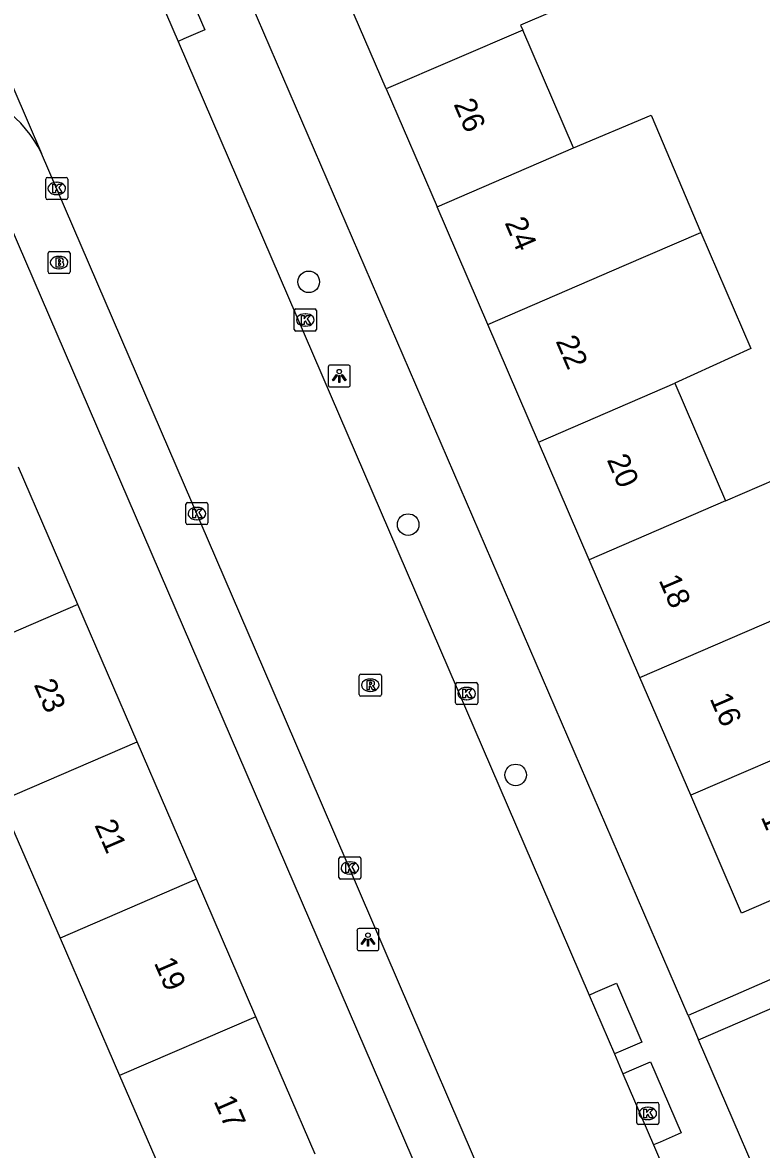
# Model space of a CAD drawing. Extents: x 159353 to 160616, y 385893 to 387321.
# Drawn here: x 159544.3 to 159577.9, y 386254.5 to 386305.6 of the extents above; entities that cross this region are included whole.
import ezdxf

# ---------------------------------------------------------------- set-up
doc = ezdxf.new("R2010")
doc.units = 0
for name, color, linetype in [('IMGEO_Boom', 7, 'Continuous'), ('IMGEO_Brandkraan', 7, 'Continuous'), ('IMGEO_Kolk', 7, 'Continuous'), ('IMGEO_Lichtpunt', 7, 'Continuous'), ('IMGEO_Pand', 7, 'Continuous'), ('IMGEO_Pand_nummerreeks', 7, 'Continuous'), ('IMGEO_Rijbaan_lokaal_gesloten', 7, 'Continuous'), ('IMGEO_Rijbaan_lokaal_open', 7, 'Continuous'), ('IMGEO_Rioolput', 7, 'Continuous'), ('IMGEO_Voetpad_open', 7, 'Continuous')]:
    doc.layers.add(name, color=color, linetype=linetype)

msp = doc.modelspace()

# ---------------------------------------------------------------- linework, layer by layer
at = {"layer": 'IMGEO_Boom'}
for centre in [(159557.321, 386293.872), (159561.831, 386282.862), (159566.708, 386271.508)]:
    msp.add_circle(centre, 0.489, dxfattribs=at)
at = {"layer": 'IMGEO_Brandkraan'}
for p, q in [((159545.496, 386294.321), (159545.496, 386295.173)), ((159545.571, 386295.247), (159546.423, 386295.247)), ((159545.984, 386295.027), (159546.009, 386295.027)), ((159546.497, 386295.173), (159546.497, 386294.321)), ((159546.007, 386294.467), (159545.982, 386294.467)), ((159546.423, 386294.247), (159545.571, 386294.247))]:
    msp.add_line(p, q, dxfattribs=at)
for points in [[(159545.496, 386294.321), (159545.496, 386295.173)], [(159545.571, 386295.247), (159546.423, 386295.247)], [(159545.844, 386294.947), (159545.844, 386294.547), (159546.057, 386294.547)], [(159546.075, 386294.947), (159545.844, 386294.947)], [(159546.497, 386295.173), (159546.497, 386294.321)], [(159546.023, 386294.866), (159545.969, 386294.866), (159545.969, 386294.79)], [(159545.969, 386294.79), (159546.022, 386294.79)], [(159546.031, 386294.714), (159545.969, 386294.714), (159545.969, 386294.633)], [(159545.969, 386294.633), (159546.031, 386294.633)], [(159546.423, 386294.247), (159545.571, 386294.247)]]:
    msp.add_lwpolyline(points, dxfattribs=at)
for centre, radius, start, end in [((159545.573, 386295.171), 0.0765, 91.552, 178.448), ((159545.573, 386295.171), 0.0765, 91.552, 178.448), ((159546.079, 386294.802), 0.145, 59.4692, 91.5367), ((159546.104, 386294.849), 0.0922, 285.5137, 58.1501), ((159546.421, 386295.171), 0.0765, 1.552, 88.448), ((159546.421, 386295.171), 0.0765, 1.552, 88.448), ((159546.024, 386294.828), 0.0379, 267.8285, 90.9355), ((159546.032, 386294.673), 0.0404, 269.8759, 90.5077), ((159546.063, 386294.798), 0.251, 268.6676, 293.5347), ((159546.109, 386294.657), 0.105, 301.3115, 78.989), ((159545.573, 386294.323), 0.0765, 181.552, 268.448), ((159545.573, 386294.323), 0.0765, 181.552, 268.448), ((159546.421, 386294.323), 0.0765, 271.552, 358.448), ((159546.421, 386294.323), 0.0765, 271.552, 358.448)]:
    msp.add_arc(centre, radius, start, end, dxfattribs=at)
for centre, major_axis, ratio, start_param, end_param in [((159545.983, 386294.747), (-0.387, 0.002), 0.722429, 4.712389, 7.853982), ((159546.008, 386294.747), (-0.39, 0.002), 0.717154, 1.570796, 4.712389)]:
    msp.add_ellipse(centre, major_axis=major_axis, ratio=ratio, start_param=start_param, end_param=end_param, dxfattribs=at)
at = {"layer": 'IMGEO_Kolk'}
for p, q in [((159545.39, 386297.68), (159545.39, 386298.532)), ((159545.465, 386298.606), (159546.317, 386298.606)), ((159546.391, 386298.532), (159546.391, 386297.68)), ((159545.878, 386298.386), (159545.903, 386298.386)), ((159546.317, 386297.606), (159545.465, 386297.606)), ((159545.901, 386297.826), (159545.876, 386297.826)), ((159556.665, 386291.716), (159556.665, 386292.568)), ((159556.74, 386292.642), (159557.592, 386292.642)), ((159557.153, 386292.422), (159557.178, 386292.422)), ((159557.666, 386292.568), (159557.666, 386291.716)), ((159557.176, 386291.862), (159557.151, 386291.862)), ((159557.592, 386291.642), (159556.74, 386291.642)), ((159551.746, 386282.935), (159551.746, 386283.787)), ((159551.821, 386283.861), (159552.673, 386283.861)), ((159552.234, 386283.641), (159552.259, 386283.641)), ((159552.747, 386283.787), (159552.747, 386282.935)), ((159552.673, 386282.861), (159551.821, 386282.861)), ((159552.257, 386283.081), (159552.232, 386283.081)), ((159563.985, 386274.771), (159563.985, 386275.623)), ((159564.06, 386275.697), (159564.912, 386275.697)), ((159564.473, 386275.477), (159564.498, 386275.477)), ((159564.986, 386275.623), (159564.986, 386274.771)), ((159564.912, 386274.697), (159564.06, 386274.697)), ((159564.496, 386274.917), (159564.471, 386274.917)), ((159558.762, 386267.787), (159559.614, 386267.787)), ((159558.687, 386266.861), (159558.687, 386267.713)), ((159559.175, 386267.567), (159559.2, 386267.567)), ((159559.688, 386267.713), (159559.688, 386266.861)), ((159559.614, 386266.787), (159558.762, 386266.787)), ((159559.198, 386267.007), (159559.173, 386267.007)), ((159572.203, 386255.727), (159572.203, 386256.579)), ((159572.278, 386256.653), (159573.13, 386256.653)), ((159573.204, 386256.579), (159573.204, 386255.727)), ((159572.691, 386256.433), (159572.716, 386256.433)), ((159573.13, 386255.653), (159572.278, 386255.653)), ((159572.714, 386255.873), (159572.689, 386255.873))]:
    msp.add_line(p, q, dxfattribs=at)
for points in [[(159545.39, 386297.68), (159545.39, 386298.532)], [(159545.465, 386298.606), (159546.317, 386298.606)], [(159546.391, 386298.532), (159546.391, 386297.68)], [(159545.711, 386298.306), (159545.834, 386298.306), (159545.834, 386298.155), (159545.964, 386298.306), (159546.128, 386298.306), (159545.982, 386298.155), (159546.135, 386297.906), (159545.983, 386297.906), (159545.898, 386298.07), (159545.834, 386298.003), (159545.834, 386297.906), (159545.711, 386297.906), (159545.711, 386298.306)], [(159546.317, 386297.606), (159545.465, 386297.606)], [(159556.665, 386291.716), (159556.665, 386292.568)], [(159556.74, 386292.642), (159557.592, 386292.642)], [(159556.986, 386292.342), (159557.109, 386292.342), (159557.109, 386292.191), (159557.239, 386292.342), (159557.403, 386292.342), (159557.257, 386292.191), (159557.41, 386291.942), (159557.258, 386291.942), (159557.173, 386292.106), (159557.109, 386292.039), (159557.109, 386291.942), (159556.986, 386291.942), (159556.986, 386292.342)], [(159557.666, 386292.568), (159557.666, 386291.716)], [(159557.592, 386291.642), (159556.74, 386291.642)], [(159551.746, 386282.935), (159551.746, 386283.787)], [(159551.821, 386283.861), (159552.673, 386283.861)], [(159552.747, 386283.787), (159552.747, 386282.935)], [(159552.067, 386283.561), (159552.19, 386283.561), (159552.19, 386283.41), (159552.32, 386283.561), (159552.484, 386283.561), (159552.338, 386283.41), (159552.491, 386283.161), (159552.339, 386283.161), (159552.254, 386283.325), (159552.19, 386283.258), (159552.19, 386283.161), (159552.067, 386283.161), (159552.067, 386283.561)], [(159552.673, 386282.861), (159551.821, 386282.861)], [(159563.985, 386274.771), (159563.985, 386275.623)], [(159564.06, 386275.697), (159564.912, 386275.697)], [(159564.986, 386275.623), (159564.986, 386274.771)], [(159564.306, 386275.397), (159564.429, 386275.397), (159564.429, 386275.246), (159564.559, 386275.397), (159564.723, 386275.397), (159564.577, 386275.246), (159564.73, 386274.997), (159564.578, 386274.997), (159564.493, 386275.161), (159564.429, 386275.094), (159564.429, 386274.997), (159564.306, 386274.997), (159564.306, 386275.397)], [(159564.912, 386274.697), (159564.06, 386274.697)], [(159558.762, 386267.787), (159559.614, 386267.787)], [(159558.687, 386266.861), (159558.687, 386267.713)], [(159559.008, 386267.487), (159559.131, 386267.487), (159559.131, 386267.336), (159559.261, 386267.487), (159559.425, 386267.487), (159559.279, 386267.336), (159559.432, 386267.087), (159559.28, 386267.087), (159559.195, 386267.251), (159559.131, 386267.184), (159559.131, 386267.087), (159559.008, 386267.087), (159559.008, 386267.487)], [(159559.688, 386267.713), (159559.688, 386266.861)], [(159559.614, 386266.787), (159558.762, 386266.787)], [(159572.203, 386255.727), (159572.203, 386256.579)], [(159572.278, 386256.653), (159573.13, 386256.653)], [(159573.204, 386256.579), (159573.204, 386255.727)], [(159572.524, 386256.353), (159572.647, 386256.353), (159572.647, 386256.202), (159572.777, 386256.353), (159572.941, 386256.353), (159572.795, 386256.202), (159572.948, 386255.953), (159572.796, 386255.953), (159572.711, 386256.117), (159572.647, 386256.05), (159572.647, 386255.953), (159572.524, 386255.953), (159572.524, 386256.353)], [(159573.13, 386255.653), (159572.278, 386255.653)]]:
    msp.add_lwpolyline(points, dxfattribs=at)
for centre, start, end in [((159545.467, 386298.53), 91.552, 178.448), ((159545.467, 386298.53), 91.552, 178.448), ((159546.315, 386298.53), 1.552, 88.448), ((159546.315, 386298.53), 1.552, 88.448), ((159545.467, 386297.682), 181.552, 268.448), ((159545.467, 386297.682), 181.552, 268.448), ((159546.315, 386297.682), 271.552, 358.448), ((159546.315, 386297.682), 271.552, 358.448), ((159556.742, 386292.566), 91.552, 178.448), ((159556.742, 386292.566), 91.552, 178.448), ((159557.59, 386292.566), 1.552, 88.448), ((159557.59, 386292.566), 1.552, 88.448), ((159556.742, 386291.718), 181.552, 268.448), ((159556.742, 386291.718), 181.552, 268.448), ((159557.59, 386291.718), 271.552, 358.448), ((159557.59, 386291.718), 271.552, 358.448), ((159551.823, 386283.785), 91.552, 178.448), ((159551.823, 386283.785), 91.552, 178.448), ((159552.671, 386283.785), 1.552, 88.448), ((159552.671, 386283.785), 1.552, 88.448), ((159551.823, 386282.937), 181.552, 268.448), ((159551.823, 386282.937), 181.552, 268.448), ((159552.671, 386282.937), 271.552, 358.448), ((159552.671, 386282.937), 271.552, 358.448), ((159564.062, 386275.621), 91.552, 178.448), ((159564.062, 386275.621), 91.552, 178.448), ((159564.91, 386275.621), 1.552, 88.448), ((159564.91, 386275.621), 1.552, 88.448), ((159564.062, 386274.773), 181.552, 268.448), ((159564.062, 386274.773), 181.552, 268.448), ((159564.91, 386274.773), 271.552, 358.448), ((159564.91, 386274.773), 271.552, 358.448), ((159558.764, 386267.711), 91.552, 178.448), ((159558.764, 386267.711), 91.552, 178.448), ((159559.612, 386267.711), 1.552, 88.448), ((159559.612, 386267.711), 1.552, 88.448), ((159558.764, 386266.863), 181.552, 268.448), ((159558.764, 386266.863), 181.552, 268.448), ((159559.612, 386266.863), 271.552, 358.448), ((159559.612, 386266.863), 271.552, 358.448), ((159572.28, 386256.577), 91.552, 178.448), ((159572.28, 386256.577), 91.552, 178.448), ((159573.128, 386256.577), 1.552, 88.448), ((159573.128, 386256.577), 1.552, 88.448), ((159572.28, 386255.729), 181.552, 268.448), ((159572.28, 386255.729), 181.552, 268.448), ((159573.128, 386255.729), 271.552, 358.448), ((159573.128, 386255.729), 271.552, 358.448)]:
    msp.add_arc(centre, 0.0765, start, end, dxfattribs=at)
for centre, major_axis, ratio, start_param, end_param in [((159545.877, 386298.106), (-0.387, 0.002), 0.722429, 4.712389, 7.853982), ((159545.902, 386298.106), (-0.39, 0.002), 0.717154, 1.570796, 4.712389), ((159557.152, 386292.142), (-0.387, 0.002), 0.722429, 4.712389, 7.853982), ((159557.177, 386292.142), (-0.39, 0.002), 0.717154, 1.570796, 4.712389), ((159552.233, 386283.361), (-0.387, 0.002), 0.722429, 4.712389, 7.853982), ((159552.258, 386283.361), (-0.39, 0.002), 0.717154, 1.570796, 4.712389), ((159564.472, 386275.197), (-0.387, 0.002), 0.722429, 4.712389, 7.853982), ((159564.497, 386275.197), (-0.39, 0.002), 0.717154, 1.570796, 4.712389), ((159559.174, 386267.287), (-0.387, 0.002), 0.722429, 4.712389, 7.853982), ((159559.199, 386267.287), (-0.39, 0.002), 0.717154, 1.570796, 4.712389), ((159572.69, 386256.153), (-0.387, 0.002), 0.722429, 4.712389, 7.853982), ((159572.715, 386256.153), (-0.39, 0.002), 0.717154, 1.570796, 4.712389)]:
    msp.add_ellipse(centre, major_axis=major_axis, ratio=ratio, start_param=start_param, end_param=end_param, dxfattribs=at)
at = {"layer": 'IMGEO_Lichtpunt'}
for p, q in [((159558.207, 386290.005), (159558.207, 386289.198)), ((159558.207, 386290.005), (159558.207, 386289.198)), ((159559.109, 386290.1), (159558.301, 386290.1)), ((159559.109, 386290.1), (159558.301, 386290.1)), ((159559.203, 386289.198), (159559.203, 386290.005)), ((159559.203, 386289.198), (159559.203, 386290.005)), ((159558.301, 386289.104), (159559.109, 386289.104)), ((159558.301, 386289.104), (159559.109, 386289.104)), ((159559.511, 386264.442), (159559.511, 386263.635)), ((159559.511, 386264.442), (159559.511, 386263.635)), ((159560.413, 386264.537), (159559.605, 386264.537)), ((159560.413, 386264.537), (159559.605, 386264.537)), ((159560.507, 386263.635), (159560.507, 386264.442)), ((159560.507, 386263.635), (159560.507, 386264.442)), ((159559.605, 386263.541), (159560.413, 386263.541)), ((159559.605, 386263.541), (159560.413, 386263.541))]:
    msp.add_line(p, q, dxfattribs=at)
for points in [[(159558.581, 386289.669), (159558.62, 386289.641), (159558.432, 386289.379), (159558.394, 386289.406), (159558.581, 386289.669)], [(159558.683, 386289.621), (159558.73, 386289.621), (159558.73, 386289.299), (159558.683, 386289.299), (159558.683, 386289.621)], [(159558.793, 386289.641), (159558.831, 386289.668), (159559.018, 386289.406), (159558.979, 386289.378), (159558.793, 386289.641)], [(159559.885, 386264.106), (159559.924, 386264.078), (159559.736, 386263.816), (159559.698, 386263.843), (159559.885, 386264.106)], [(159559.987, 386264.058), (159560.034, 386264.058), (159560.034, 386263.736), (159559.987, 386263.736), (159559.987, 386264.058)], [(159560.097, 386264.078), (159560.135, 386264.105), (159560.322, 386263.843), (159560.283, 386263.815), (159560.097, 386264.078)]]:
    msp.add_lwpolyline(points, dxfattribs=at)
for centre in [(159558.706, 386289.803), (159560.01, 386264.24)]:
    msp.add_circle(centre, 0.0994, dxfattribs=at)
for centre, start, end in [((159558.301, 386290.005), 90, 180), ((159558.301, 386290.005), 90, 180), ((159559.109, 386290.005), 0, 90), ((159559.109, 386290.005), 0, 90), ((159558.301, 386289.198), 180, 270), ((159558.301, 386289.198), 180, 270), ((159559.109, 386289.198), 270, 0), ((159559.109, 386289.198), 270, 360), ((159559.605, 386264.442), 90, 180), ((159559.605, 386264.442), 90, 180), ((159560.413, 386264.442), 0, 90), ((159560.413, 386264.442), 0, 90), ((159559.605, 386263.635), 180, 270), ((159559.605, 386263.635), 180, 270), ((159560.413, 386263.635), 270, 0), ((159560.413, 386263.635), 270, 360)]:
    msp.add_arc(centre, 0.0946, start, end, dxfattribs=at)
at = {"layer": 'IMGEO_Pand'}
for points in [[(159560.839, 386302.62), (159558.418, 386308.236), (159563.01, 386310.216), (159564.608, 386310.905), (159567.402, 386312.109), (159569.724, 386306.723), (159566.929, 386305.519), (159567.028, 386305.29)], [(159567.028, 386305.29), (159560.839, 386302.62)], [(159569.33, 386299.951), (159567.028, 386305.29)], [(159560.839, 386302.62), (159563.141, 386297.281)], [(159569.33, 386299.951), (159572.856, 386301.425), (159575.103, 386296.112)], [(159563.141, 386297.281), (159569.33, 386299.951)], [(159565.442, 386291.941), (159563.141, 386297.281)], [(159565.442, 386291.941), (159571.631, 386294.612), (159575.103, 386296.112)], [(159575.103, 386296.112), (159577.376, 386290.846), (159573.933, 386289.273)], [(159567.743, 386286.603), (159565.442, 386291.941)], [(159567.743, 386286.603), (159573.933, 386289.273)], [(159573.933, 386289.273), (159576.235, 386283.934)], [(159570.045, 386281.263), (159567.743, 386286.603)], [(159546.84, 386279.234), (159544.148, 386285.464)], [(159576.235, 386283.934), (159579.319, 386285.265), (159581.623, 386279.927), (159578.536, 386278.595)], [(159576.235, 386283.934), (159570.045, 386281.263)], [(159572.346, 386275.924), (159570.045, 386281.263)], [(159546.84, 386279.234), (159540.647, 386276.559)], [(159549.532, 386273.004), (159546.84, 386279.234)], [(159572.346, 386275.924), (159578.536, 386278.595)], [(159574.648, 386270.585), (159572.346, 386275.924)], [(159580.837, 386273.256), (159583.531, 386274.419), (159585.838, 386269.075), (159583.141, 386267.912), (159581.543, 386267.223), (159576.951, 386265.243), (159574.648, 386270.585)], [(159543.345, 386270.332), (159549.532, 386273.004)], [(159552.224, 386266.774), (159549.532, 386273.004)], [(159580.837, 386273.256), (159574.648, 386270.585)], [(159543.345, 386270.332), (159546.044, 386264.104)], [(159552.224, 386266.774), (159546.044, 386264.104)], [(159554.916, 386260.543), (159552.224, 386266.774)], [(159546.044, 386264.104), (159548.742, 386257.876)], [(159554.916, 386260.543), (159548.742, 386257.876)], [(159557.608, 386254.313), (159554.916, 386260.543)], [(159548.742, 386257.876), (159551.44, 386251.649)]]:
    msp.add_lwpolyline(points, dxfattribs=at)
at = {"layer": 'IMGEO_Rijbaan_lokaal_gesloten'}
for points in [[(159538.567, 386315.088), (159538.773, 386314.614), (159545.199, 386299.697)], [(159550.003, 386308.002), (159551.394, 386304.776)], [(159551.394, 386304.776), (159567.886, 386266.536), (159570.042, 386261.524)], [(159565.922, 386251.602), (159555.665, 386275.434), (159545.199, 386299.697)], [(159570.042, 386261.524), (159571.189, 386258.857)], [(159571.189, 386258.857), (159571.577, 386257.955)], [(159571.577, 386257.955), (159572.965, 386254.727)], [(159572.965, 386254.727), (159577.078, 386245.165), (159584.17, 386228.799), (159587.984, 386220.031)]]:
    msp.add_lwpolyline(points, dxfattribs=at)
at = {"layer": 'IMGEO_Rijbaan_lokaal_open'}
msp.add_arc((159540.144, 386297.229), 5.625, 26.0169, 80.1493, dxfattribs=at)
at = {"layer": 'IMGEO_Rioolput'}
for p, q in [((159559.614, 386275.152), (159559.614, 386276.004)), ((159559.689, 386276.078), (159560.541, 386276.078)), ((159560.615, 386276.004), (159560.615, 386275.152)), ((159560.102, 386275.858), (159560.127, 386275.858)), ((159560.541, 386275.078), (159559.689, 386275.078)), ((159560.125, 386275.298), (159560.1, 386275.298))]:
    msp.add_line(p, q, dxfattribs=at)
for points in [[(159559.614, 386275.152), (159559.614, 386276.004)], [(159559.689, 386276.078), (159560.541, 386276.078)], [(159560.615, 386276.004), (159560.615, 386275.152)], [(159560.203, 386275.776), (159559.951, 386275.778), (159559.951, 386275.378)], [(159559.951, 386275.378), (159560.075, 386275.378), (159560.075, 386275.54), (159560.086, 386275.54)], [(159560.129, 386275.697), (159560.075, 386275.697), (159560.075, 386275.616)], [(159560.075, 386275.616), (159560.127, 386275.616)], [(159560.133, 386275.511), (159560.204, 386275.378), (159560.344, 386275.378), (159560.279, 386275.504)], [(159560.541, 386275.078), (159559.689, 386275.078)]]:
    msp.add_lwpolyline(points, dxfattribs=at)
for centre, radius, start, end in [((159559.691, 386276.002), 0.0765, 91.552, 178.448), ((159559.691, 386276.002), 0.0765, 91.552, 178.448), ((159560.539, 386276.002), 0.0765, 1.552, 88.448), ((159560.539, 386276.002), 0.0765, 1.552, 88.448), ((159560.085, 386275.487), 0.0533, 26.0293, 88.6989), ((159560.111, 386275.805), 0.19, 274.7715, 282.9687), ((159560.135, 386275.601), 0.0964, 77.0061, 93.1865), ((159560.149, 386275.658), 0.0378, 276.6634, 79.6772), ((159560.202, 386275.666), 0.109, 350.3612, 89.416), ((159560.2, 386275.666), 0.112, 277.5842, 350.9817), ((159560.184, 386275.451), 0.108, 29.5134, 73.7905), ((159559.691, 386275.154), 0.0765, 181.552, 268.448), ((159559.691, 386275.154), 0.0765, 181.552, 268.448), ((159560.539, 386275.154), 0.0765, 271.552, 358.448), ((159560.539, 386275.154), 0.0765, 271.552, 358.448)]:
    msp.add_arc(centre, radius, start, end, dxfattribs=at)
for centre, major_axis, ratio, start_param, end_param in [((159560.101, 386275.578), (-0.387, 0.002), 0.722429, 4.712389, 7.853982), ((159560.126, 386275.578), (-0.39, 0.002), 0.717154, 1.570796, 4.712389)]:
    msp.add_ellipse(centre, major_axis=major_axis, ratio=ratio, start_param=start_param, end_param=end_param, dxfattribs=at)
at = {"layer": 'IMGEO_Voetpad_open'}
for points in [[(159574.53, 386260.594), (159553.272, 386309.836)], [(159550.003, 386308.002), (159550.259, 386308.112), (159551.214, 386308.525), (159552.608, 386305.301), (159551.653, 386304.888), (159551.394, 386304.776)], [(159542.657, 386298.98), (159563.791, 386250), (159564.438, 386248.501)], [(159595.973, 386275.922), (159598.082, 386270.879), (159574.53, 386260.594)], [(159575.005, 386259.494), (159598.598, 386269.679), (159601.044, 386263.997)], [(159570.042, 386261.524), (159570.331, 386261.648), (159571.286, 386262.06), (159572.436, 386259.394), (159571.481, 386258.982), (159571.189, 386258.857)], [(159574.53, 386260.594), (159575.005, 386259.494)], [(159591.643, 386220.955), (159579.104, 386250), (159575.005, 386259.494)], [(159571.577, 386257.955), (159571.87, 386258.081), (159572.825, 386258.493), (159574.217, 386255.267), (159573.262, 386254.855), (159572.965, 386254.727)]]:
    msp.add_lwpolyline(points, dxfattribs=at)

# ---------------------------------------------------------------- texts
at = {"layer": 'IMGEO_Pand_nummerreeks'}
for s, rotation, p in [('26', 293.3194, (159563.88, 386301.932)), ('24', 293.3192, (159566.197, 386296.557)), ('22', 293.3192, (159568.511, 386291.186)), ('20', 293.3194, (159570.831, 386285.806)), ('18', 293.3192, (159573.184, 386280.347)), ('23', 293.3684, (159544.835, 386275.605)), ('16', 293.3194, (159575.499, 386274.977)), ('21', 293.3684, (159547.588, 386269.234)), ('14', 293.3192, (159577.816, 386269.602)), ('19', 293.3684, (159550.287, 386262.987)), ('17', 293.3684, (159552.995, 386256.72))]:
    msp.add_text(s, height=1, rotation=rotation, dxfattribs=at).set_placement(p)

doc.saveas('drawing.dxf')
